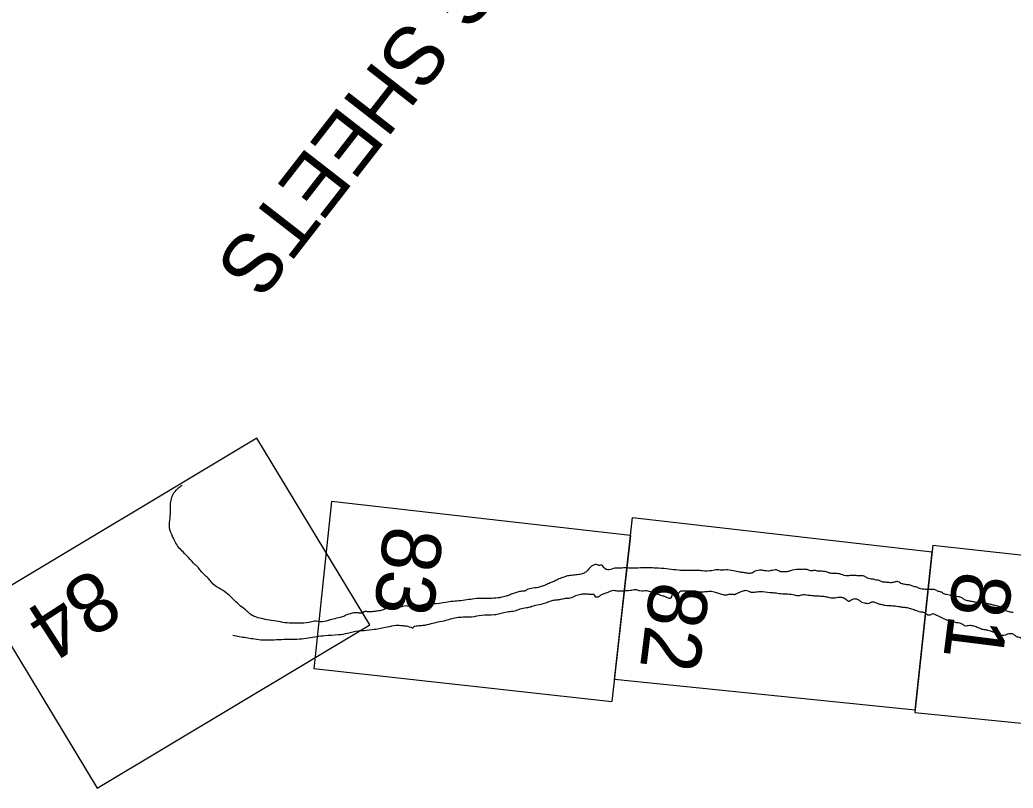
# Model space of a CAD drawing. Extents: x 3888273 to 3909528, y 158682 to 181032.
# Drawn here: x 3892136 to 3893120, y 169287 to 170048 of the extents above; entities that cross this region are included whole.
import ezdxf

# ---------------------------------------------------------------- set-up
doc = ezdxf.new("R2010")
doc.units = 0
doc.layers.add('V-ANNO-NPLT', color=7, linetype='Continuous')

msp = doc.modelspace()

# ---------------------------------------------------------------- linework, layer by layer
at = {"layer": 'V-ANNO-NPLT'}
for points in [[(3892370.82, 169633.3), (3892100.68, 169471.68), (3892212.71, 169286.74), (3892482.99, 169448.4)], [(3892482.99, 169448.4), (3892370.82, 169633.3)], [(3892741.16, 169537.07), (3892444.85, 169570.67), (3892439.63, 169520.75)], [(3892725.33, 169394.48), (3892743.14, 169554.97), (3893040.31, 169520.73)], [(3892741.16, 169537.07), (3892722.91, 169372.7)], [(3893041.02, 169527.31), (3893023.13, 169361.65), (3893320.38, 169331.99)], [(3893041.02, 169527.31), (3893337.62, 169494.82)], [(3892439.63, 169520.75), (3892428.79, 169417.13)], [(3893023.37, 169363.86), (3893040.31, 169520.73)], [(3892428.79, 169417.13), (3892427.53, 169405.11), (3892722.91, 169372.7)], [(3893023.37, 169363.86), (3892725.33, 169394.48)]]:
    msp.add_lwpolyline(points, dxfattribs=at)
for points in [[(3892309.71, 169507.93), (3892303.3, 169515.15), (3892297.87, 169520.69), (3892293.33, 169525.53), (3892290.02, 169530.82), (3892286.69, 169537.88), (3892284.32, 169546.48), (3892284.98, 169553.8), (3892285.29, 169559.96), (3892285.46, 169567.39), (3892286.27, 169573.43), (3892288.88, 169579.19), (3892293.78, 169584.54), (3892297.12, 169586.91)], [(3892361.19, 169461.99), (3892348.77, 169472.6), (3892337.74, 169482.38), (3892329.65, 169487.16), (3892322.73, 169494.65), (3892315.33, 169502.08), (3892312.34, 169505.95), (3892309.71, 169507.93)], [(3892709.78, 169507.34), (3892707.17, 169508.32), (3892705.24, 169507.94), (3892702.52, 169506.57), (3892697.54, 169501.21), (3892694.5, 169499.46), (3892689.97, 169498.26), (3892684.3, 169497.66), (3892678.83, 169496.9), (3892675.36, 169495.82), (3892670.36, 169494.03), (3892665.94, 169491.77), (3892662.67, 169490.53), (3892658.41, 169488.47), (3892653.76, 169486.72), (3892649.78, 169485.41), (3892646.59, 169485.07), (3892639.06, 169483.38), (3892637.21, 169482.29), (3892633.51, 169481.71), (3892629.29, 169480.91), (3892625.31, 169479.59), (3892621.02, 169477.88), (3892617.9, 169476.84), (3892615.46, 169476.22), (3892612.66, 169475.57), (3892611.8, 169475.3)], [(3892804.21, 169502.29), (3892795.44, 169502.26), (3892786.23, 169502.89), (3892776.99, 169503.89), (3892766.33, 169504.73), (3892760.03, 169504.96), (3892751.25, 169504.92), (3892741.61, 169504.62), (3892737.28, 169504.88), (3892731.02, 169504.75), (3892725.67, 169504.55), (3892719.92, 169503.04), (3892714.85, 169505.19), (3892713.56, 169507.21), (3892711.2, 169507.49), (3892709.78, 169507.34)], [(3892862.17, 169500.05), (3892861.46, 169499.75), (3892858.27, 169499.41), (3892854.26, 169500.06), (3892850.45, 169500.55), (3892845.14, 169501.6), (3892837.47, 169502.94), (3892830.15, 169502.7), (3892827.44, 169502.95), (3892821.61, 169502.16), (3892812.67, 169501.93), (3892809.96, 169502.18), (3892806.53, 169502.36), (3892804.21, 169502.29)], [(3892872.52, 169502.44), (3892870.41, 169502.78), (3892867.54, 169502.39), (3892864.9, 169501.71), (3892863.18, 169500.83), (3892862.17, 169500.05)], [(3892921.94, 169501.9), (3892920.37, 169501.86), (3892917.03, 169502.94), (3892913.56, 169503.47), (3892909.63, 169503.41), (3892901.83, 169502.59), (3892897.14, 169501.2), (3892892.69, 169500.9), (3892889.08, 169501.24), (3892887.15, 169502.47), (3892881.96, 169502.46), (3892877.19, 169501.77), (3892873.93, 169502.14), (3892872.52, 169502.44)], [(3892935.34, 169500.94), (3892932.22, 169501.43), (3892929.26, 169501.79), (3892925.62, 169501.92), (3892923.34, 169502.32), (3892921.94, 169501.9)], [(3892973.96, 169496.04), (3892972.71, 169496.65), (3892971.05, 169497.02), (3892966.92, 169497.12), (3892962.95, 169497.41), (3892958.66, 169497.31), (3892954.56, 169497.06), (3892948.63, 169498.94), (3892943.75, 169499.32), (3892939.78, 169499.62), (3892937.03, 169500.22), (3892935.34, 169500.94)], [(3892982.05, 169493.6), (3892980.56, 169493.67), (3892978.75, 169494.12), (3892976.27, 169494.79), (3892975.39, 169495.16), (3892973.96, 169496.04)], [(3893048.93, 169480.89), (3893045.59, 169481.97), (3893042.21, 169483.41), (3893037.72, 169483.47), (3893031.78, 169483.74), (3893028.67, 169484.3), (3893024.94, 169485.7), (3893021.05, 169486.9), (3893017.51, 169488.14), (3893014.09, 169488.31), (3893011.89, 169488.8), (3893008.35, 169490.03), (3893006.43, 169491.26), (3893003.59, 169490.96), (3892999.73, 169490.2), (3892994.86, 169490.58), (3892991.24, 169490.91), (3892988.41, 169492.22), (3892984.75, 169492.91), (3892982.05, 169493.6)], [(3892785.35, 169479.33), (3892782.31, 169477.58), (3892781.75, 169476.08), (3892780.64, 169474.71), (3892778.83, 169474.88), (3892776.01, 169476.19), (3892772.67, 169477.27), (3892767.28, 169479.03), (3892762.25, 169480.83), (3892757.46, 169482.11), (3892750.65, 169482.11), (3892747.5, 169483.03), (3892742.35, 169482.66), (3892739.35, 169482.17), (3892734, 169481.96), (3892729, 169481.79), (3892724.99, 169482.44), (3892716.67, 169479.77), (3892713.21, 169478.68), (3892709.22, 169475.75)], [(3892611.8, 169475.3), (3892603.8, 169474.63), (3892598.81, 169474.46), (3892592.51, 169474.69), (3892577.12, 169472.88), (3892561.52, 169471.23), (3892549, 169469.37), (3892539.71, 169469.1), (3892531.99, 169467.57), (3892524.95, 169466.46), (3892518.42, 169467.2)], [(3892709.24, 169475.77), (3892708.49, 169475.85), (3892707.04, 169476.06), (3892705.59, 169477.88), (3892701.38, 169478.69), (3892697.05, 169478.94), (3892691.9, 169478.58), (3892686.85, 169477.15), (3892681.18, 169474.93), (3892676.57, 169474.45), (3892672, 169473.61), (3892667.24, 169472.92), (3892663.18, 169472.31), (3892659.4, 169470.84), (3892654.55, 169469.25), (3892647.03, 169467.56), (3892642.34, 169466.17), (3892638.32, 169465.2), (3892631.47, 169463.94), (3892626.3, 169461.96), (3892620.63, 169461.36), (3892614.33, 169459.98), (3892611.69, 169459.52)], [(3892844.66, 169478.3), (3892842.41, 169478.56), (3892839.53, 169478.62), (3892835.32, 169477.81), (3892830.72, 169478.94), (3892826.63, 169480.3), (3892821.68, 169481.38), (3892816.33, 169481.18), (3892810.62, 169480.93), (3892806.64, 169481.23), (3892799.6, 169481.73), (3892794.21, 169481.88), (3892790.16, 169481.27), (3892788.22, 169479.28), (3892785.35, 169479.33)], [(3892903.4, 169477.85), (3892897.21, 169478.81), (3892891.82, 169478.95), (3892885.64, 169479.73), (3892879.31, 169480.32), (3892869.91, 169481.11), (3892864.04, 169480.67), (3892860.81, 169480.69), (3892855.08, 169482.41), (3892851.77, 169481.52), (3892846.96, 169479.58), (3892845.93, 169479.11), (3892843.92, 169477.83)], [(3892950.71, 169475.47), (3892946.84, 169475.46), (3892944.2, 169475), (3892938.61, 169475.31), (3892934.21, 169476.27), (3892928.43, 169476.74), (3892925, 169476.91), (3892920.84, 169477.37), (3892916.86, 169477.66), (3892914.3, 169478.11), (3892911.27, 169477.97), (3892907.41, 169477.2), (3892904.86, 169477.65), (3892903.4, 169477.85)], [(3893034.47, 169458.91), (3893031.73, 169460.8), (3893029.92, 169460.96), (3893024.57, 169462.37), (3893020.09, 169464.04), (3893015.65, 169465.37), (3893011.32, 169465.62), (3893008.21, 169466.19), (3893002.39, 169467.01), (3892997.16, 169467.35), (3892993.74, 169467.53), (3892990.24, 169468.41), (3892986.74, 169469.29), (3892981.35, 169471.05), (3892978.75, 169470.24), (3892977.57, 169469.58), (3892973.4, 169470.03), (3892970.65, 169470.64), (3892968.3, 169472.54), (3892965.47, 169473.85), (3892961.18, 169473.75), (3892959.01, 169472.27), (3892957.82, 169471.61), (3892955.31, 169473.31), (3892953.59, 169474.38), (3892951.9, 169475.1), (3892950.6, 169475.5)], [(3893120.43, 169460.69), (3893116.42, 169461.34), (3893112.33, 169462.7), (3893109.7, 169463.85), (3893106.17, 169466.71), (3893101.57, 169467.83), (3893098.07, 169468.71), (3893095.87, 169469.2), (3893092.02, 169470.04), (3893086.07, 169470.31), (3893082.97, 169470.88), (3893079.66, 169471.6), (3893076.2, 169472.13), (3893072.31, 169473.33), (3893069.6, 169475.2), (3893066.26, 169476.28), (3893063.16, 169476.84), (3893059.85, 169477.57), (3893057.14, 169477.82), (3893054.39, 169478.42), (3893051.05, 169479.5), (3893049.48, 169480.77), (3893048.93, 169480.89)], [(3892518.42, 169467.2), (3892515.34, 169466.74), (3892512.21, 169465.65), (3892509.51, 169465.12), (3892506.49, 169465.3), (3892503.69, 169465.76), (3892498.36, 169464.19), (3892495.22, 169463.11), (3892490.33, 169462.09), (3892486.37, 169461.67), (3892481.64, 169461.42), (3892478.13, 169461.55), (3892474.77, 169460.19), (3892471.25, 169460.32), (3892467.74, 169460.45), (3892463.34, 169459.48), (3892458.99, 169458.02), (3892457.28, 169456.85)], [(3892457.28, 169456.85), (3892449.91, 169454.95), (3892443.64, 169453.32), (3892435.77, 169451.52), (3892427.99, 169451.98), (3892422.96, 169450.81), (3892412.24, 169450.15), (3892403.21, 169450.16), (3892394.55, 169451.34), (3892385.53, 169452.8), (3892377.15, 169454.33), (3892370.68, 169456.07), (3892366.3, 169457.86), (3892362.07, 169461.28), (3892361.19, 169461.99)], [(3892611.74, 169459.53), (3892606.45, 169458.25), (3892593.78, 169457.8), (3892583.74, 169456.2), (3892570.35, 169455.68), (3892557.95, 169452.76), (3892543.25, 169449.41), (3892535.38, 169447.68), (3892530.22, 169447.31), (3892525.41, 169445.37), (3892525.3, 169444.98)], [(3893093.97, 169443.38), (3893089.78, 169444.01), (3893085.85, 169445.57), (3893081.57, 169447.08), (3893077.2, 169447.7), (3893072.56, 169447.56), (3893070.05, 169449.27), (3893064.35, 169450.63), (3893060.5, 169451.48), (3893055.7, 169452.76), (3893052.52, 169454.04), (3893047.21, 169456.7), (3893044.19, 169458.18), (3893041.56, 169459.33), (3893039.12, 169458.71), (3893036.87, 169457.94), (3893035.18, 169458.65), (3893034.47, 169458.91)], [(3892525.35, 169445.21), (3892518.94, 169447.11), (3892515.15, 169447.46), (3892509.11, 169447.82), (3892500.04, 169446.11), (3892487.28, 169443.76), (3892477.39, 169442.71), (3892471.67, 169442.36), (3892460.68, 169439.94), (3892451.83, 169438.5), (3892438.41, 169437.59), (3892430.5, 169436.75)], [(3893183.37, 169434.28), (3893181.57, 169433.48), (3893180.94, 169432.7), (3893176.49, 169432.4), (3893171.85, 169432.27), (3893164.84, 169432.43), (3893158.82, 169431.79), (3893150.16, 169432.31), (3893147.09, 169432.52), (3893145.48, 169432.53), (3893144.85, 169431.74), (3893144.73, 169431.19), (3893142.05, 169431.09), (3893138.39, 169431.78), (3893134.27, 169433.49), (3893130.81, 169434.02), (3893126.84, 169435.93), (3893122.95, 169437.13), (3893121.15, 169438.91), (3893117.84, 169439.64), (3893114.85, 169439.14), (3893112.45, 169438.17), (3893109.77, 169438.06), (3893105.52, 169439.23), (3893101.6, 169440.78), (3893098.02, 169442.37), (3893095.27, 169442.98), (3893093.97, 169443.38)], [(3892430.5, 169436.75), (3892413.27, 169434.17), (3892402.28, 169434.01), (3892383.59, 169433.28), (3892375.08, 169433.38), (3892366.95, 169434.53), (3892353.72, 169436.63), (3892347.08, 169437.92)]]:
    msp.add_spline(points, degree=3, dxfattribs=at)

# ---------------------------------------------------------------- texts
for s, height, rotation, p in [('INDEX TO ADJOINING SHEETS', 58.33, 232.11481, (3893033.82, 170710.78)), ('83', 58.5, 262.82672, (3892497.8, 169548.16)), ('84', 58.5, 212.82671, (3892210.58, 169506.53)), ('81', 58.5, 262.82672, (3893062.16, 169503.27)), ('82', 58.5, 262.82672, (3892761.48, 169492.81))]:
    msp.add_text(s, height=height, rotation=rotation, dxfattribs=at).set_placement(p)

doc.saveas('drawing.dxf')
